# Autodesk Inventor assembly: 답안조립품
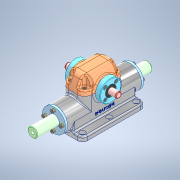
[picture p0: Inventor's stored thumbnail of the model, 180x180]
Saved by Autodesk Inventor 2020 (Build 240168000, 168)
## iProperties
Created: 2024-06
Part Number: 답안조립품
Document SubType Name: Assembly
Designer: oem
Author: oem
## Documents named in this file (13)
- C:\Users\oem\Desktop\740604V1011\답안조립품.iam
- C:\Users\oem\Desktop\740604V1011\본체.ipt
- C:\Users\oem\Desktop\740604V1011\오일레스 부시.ipt
- C:\Users\oem\Desktop\740604V1011\부시 커버.ipt
- C:\Users\oem\Desktop\740604V1011\스프링 와셔 M4.ipt
- C:\Users\oem\Desktop\740604V1011\육각 소켓 머리 볼트 M4x10.ipt
- C:\Users\oem\Desktop\740604V1011\랙.ipt
- C:\Users\oem\Desktop\740604V1011\깊은 홈 볼 베어링 6901.ipt
- C:\Users\oem\Desktop\740604V1011\칼라.ipt
- C:\Users\oem\Desktop\740604V1011\피니언.ipt
- C:\Users\oem\Desktop\740604V1011\윗커버.ipt
- C:\Users\oem\Desktop\740604V1011\베어링 커버.ipt
- C:\Users\oem\Desktop\740604V1011\오일실 12 22 7.ipt
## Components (1 placed, 1 different names)
1. 피니언:1
